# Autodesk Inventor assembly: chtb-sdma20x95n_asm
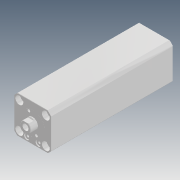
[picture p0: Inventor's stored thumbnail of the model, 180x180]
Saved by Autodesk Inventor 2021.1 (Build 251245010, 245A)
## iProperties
Created: 2018-05
Part Number: chtb-sdma20x95n_asm
Description: STEP AP214
Document SubType Name: Assembly
Designer: user
Title: chtb-sdma20x95n_asm.STEP
Revision Number: ÈÎºÎ
Sending System: SolidWorks 2016
Preprocessor: SwSTEP 2.0
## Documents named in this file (5)
- D:\Vault_2016\Projekty\Clamptek\Hydraulic\CHTB\CHTB-20\Inventor\CHTB-SDMA20x95N\chtb-sdma20x95n_asm.iam
- D:\Vault_2016\Projekty\Clamptek\Hydraulic\CHTB\CHTB-20\Inventor\CHTB-SDMA20x95N\CHTB-SDMA20X95NBT.ipt
- D:\Vault_2016\Projekty\Clamptek\Hydraulic\CHTB\CHTB-20\Inventor\CHTB-SDMA20x95N\CHTB-SDMA20X95NHSG.ipt
- D:\Vault_2016\Projekty\Clamptek\Hydraulic\CHTB\CHTB-20\Inventor\CHTB-SDMA20x95N\QG_3.ipt
- D:\Vault_2016\Projekty\Clamptek\Hydraulic\CHTB\CHTB-20\Inventor\CHTB-SDMA20x95N\socket set screw flat point_iso_ISO 4026 - M5 x 5-N.ipt
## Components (5 placed, 5 different names)
1. CHTB-SDMA20X95NBT_1
2. CHTB-SDMA20X95NHSG_2
3. QG_3_3
4. socket set screw flat point_iso_ISO 4026 - M5 x 5-N_4
5. socket set screw flat point_iso_ISO 4026 - M5 x 5-N_5
